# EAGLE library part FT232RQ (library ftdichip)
USB UART 4th Generation USB UART (USB <-> Serial) Controller
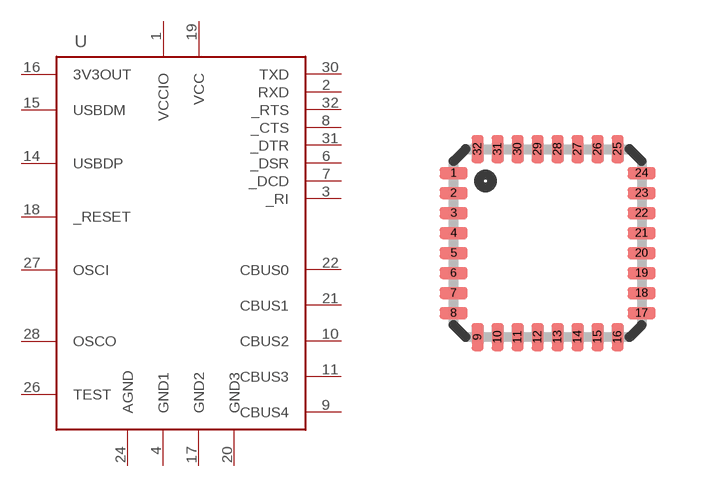
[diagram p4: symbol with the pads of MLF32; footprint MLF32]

Designator prefix -

## FT232RQ  [MLF32]
1  VCCIO  pwr
2  RXD  in
3  _RI  in
4  GND1  pwr
6  _DSR  in
7  _DCD  in
8  _CTS  in
9  CBUS4
10  CBUS2
11  CBUS3
14  USBDP
15  USBDM
16  3V3OUT  out
17  GND2  pwr
18  _RESET  in
19  VCC  pwr
20  GND3  pwr
21  CBUS1
22  CBUS0
24  AGND  pwr
26  TEST  in
27  OSCI  in
28  OSCO  out
30  TXD  out
31  _DTR  out
32  _RTS  out

## Footprint MLF32 (pad centres in mm)
32M1-A Micro Lead Frame package (MLF)
smd 0.7 x 0.3: 1 -2.35,1.75; 2 -2.35,1.25; 3 -2.35,0.75; 4 -2.35,0.25; 5 -2.35,-0.25; 6 -2.35,-0.75; 7 -2.35,-1.25; 8 -2.35,-1.75; 17 2.35,-1.75; 18 2.35,-1.25; 19 2.35,-0.75; 20 2.35,-0.25; 21 2.35,0.25; 22 2.35,0.75; 23 2.35,1.25; 24 2.35,1.75
smd 0.3 x 0.7: 9 -1.75,-2.35; 10 -1.25,-2.35; 11 -0.75,-2.35; 12 -0.25,-2.35; 13 0.25,-2.35; 14 0.75,-2.35; 15 1.25,-2.35; 16 1.75,-2.35; 25 1.75,2.35; 26 1.25,2.35; 27 0.75,2.35; 28 0.25,2.35; 29 -0.25,2.35; 30 -0.75,2.35; 31 -1.25,2.35; 32 -1.75,2.35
